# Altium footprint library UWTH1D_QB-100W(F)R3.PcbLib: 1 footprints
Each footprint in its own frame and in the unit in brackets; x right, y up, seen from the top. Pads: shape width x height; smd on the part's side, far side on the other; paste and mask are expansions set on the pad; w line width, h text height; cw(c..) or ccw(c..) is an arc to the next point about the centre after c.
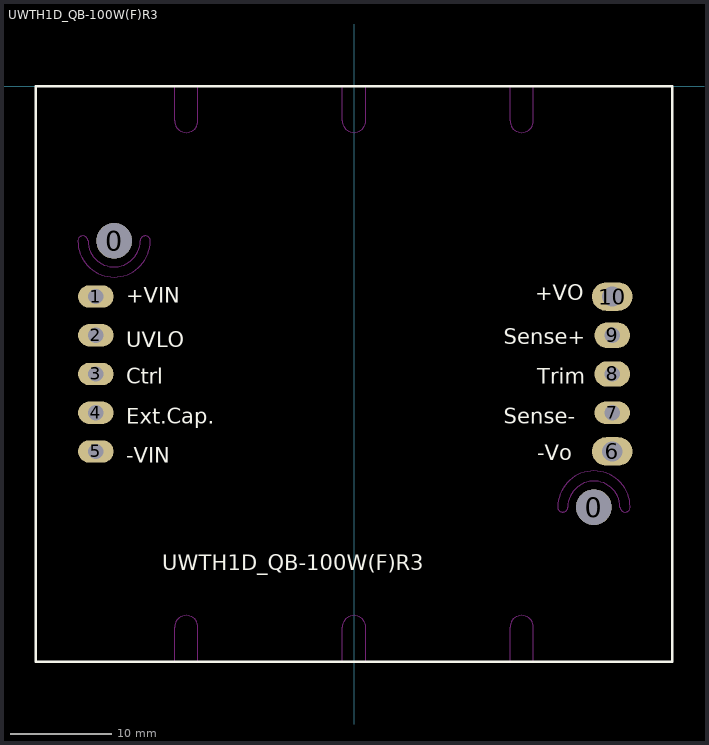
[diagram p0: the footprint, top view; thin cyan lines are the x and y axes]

## UWTH1D_QB-100W(F)R3 [mm]
pads (12):
  round 3.5 hole 3.5: 0(-23.6,-15.2) 0(23.6,-41.4)
  oval 3.5x2.2 hole 1.5: 1(-25.4,-20.68) 2(-25.4,-24.49) 3(-25.4,-28.3) 4(-25.4,-32.11) 5(-25.4,-35.92) 7(25.4,-32.11)
  oval 4x2.8 hole 2: 6(25.4,-35.92) 10(25.4,-20.68)
  oval 3.5x2.5 hole 1.5: 8(25.4,-28.3) 9(25.4,-24.49)
Top Overlay:
  lines w0.254: -31.3,-56.6 -31.3,0 31.3,0 31.3,-56.6 -31.3,-56.6
  text "Ctrl" at -22.421,-29.271 h1.52
  text "Ext.Cap." at -22.424,-33.203 h1.52
  text "+VIN" at -22.424,-21.301 h1.52
  text "UVLO" at -22.424,-25.673 h1.52
  text "-VIN" at -22.424,-37.013 h1.52
  text "-Vo" at 18.035,-36.786 h1.52
  text "Sense+" at 14.719,-25.381 h1.52
  text "Trim" at 18.021,-29.246 h1.52
  text "+VO" at 17.818,-21.05 h1.52
  text "Sense-" at 14.719,-33.177 h1.52
  text "UWTH1D_QB-100W(F)R3" at -18.878,-47.584 h1.52
Keep-Out Layer:
  lines w0.025: -26.165,-15.211 ccw(c-23.6,-15.2) -21.035,-15.213 cw(c-20.535,-15.213) -20.035,-15.213 ; -26.165,-15.215 ccw(c-26.665,-15.215) -27.165,-15.215 ccw(c-23.6,-15.2) -20.035,-15.218 ; 21.035,-41.389 cw(c23.6,-41.4) 26.165,-41.387 ccw(c26.665,-41.387) 27.165,-41.387 ; 21.035,-41.385 cw(c20.535,-41.385) 20.035,-41.385 cw(c23.6,-41.4) 27.165,-41.382 ; -17.65,-56.6 -17.65,-53.2 cw(c-16.5,-53.2) -15.35,-53.2 -15.35,-56.6 -17.65,-56.6 ; -17.65,-3.4 ccw(c-16.5,-3.4) -15.35,-3.4 -15.35,0 -17.65,0 -17.65,-3.4 ; -1.15,-56.6 -1.15,-53.2 cw(c0,-53.2) 1.15,-53.2 1.15,-56.6 -1.15,-56.6 ; -1.15,-3.4 ccw(c0,-3.4) 1.15,-3.4 1.15,0 -1.15,0 -1.15,-3.4 ; 15.35,-56.6 15.35,-53.2 cw(c16.5,-53.2) 17.65,-53.2 17.65,-56.6 15.35,-56.6 ; 15.35,-3.4 ccw(c16.5,-3.4) 17.65,-3.4 17.65,0 15.35,0 15.35,-3.4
